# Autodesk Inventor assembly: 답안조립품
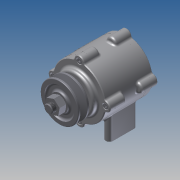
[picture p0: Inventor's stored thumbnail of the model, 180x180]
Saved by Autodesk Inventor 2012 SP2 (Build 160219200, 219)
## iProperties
Created: 2015-03
Part Number: 답안조립품
Document SubType Name: Assembly
Designer: Administrator
Author: Administrator
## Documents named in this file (11)
- C:\Users\Administrator\Desktop\450306V1034\답안조립품.iam
- C:\Users\Administrator\Desktop\450306V1034\본체.ipt
- C:\Users\Administrator\Desktop\450306V1034\커버.ipt
- C:\Users\Administrator\Desktop\450306V1034\오일실.ipt
- C:\Users\Administrator\Desktop\450306V1034\커버2.ipt
- C:\Users\Administrator\Desktop\450306V1034\축.ipt
- C:\Users\Administrator\Desktop\450306V1034\베어링 6204.ipt
- C:\Users\Administrator\Desktop\450306V1034\키(4 x 4 x 12).ipt
- C:\Users\Administrator\Desktop\450306V1034\V벨트풀리.ipt
- C:\Users\Administrator\Desktop\450306V1034\너트 M12x1.25.ipt
- C:\Users\Administrator\Desktop\450306V1034\M 4 x 12.ipt
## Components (14 placed, 6 different names)
1. KS B 2804 D D - 20 32 8:1
2. KS B 2023 6204 - 20 x 47 x 14:1
3. KS B 2023 6204 - 20 x 47 x 14:2
4. KS B 1311 (I) 4 x 4 x 12:1
5. 그루브 풀리1:1
6. KS B 1012 클래스 1 일반 - 미터 M12x1.25:1
7. KS B 1003 - 미터 M 4 x 12:1
8. KS B 1003 - 미터 M 4 x 12:3
9. KS B 1003 - 미터 M 4 x 12:4
10. KS B 1003 - 미터 M 4 x 12:5
11. KS B 1003 - 미터 M 4 x 12:2
12. KS B 1003 - 미터 M 4 x 12:6
13. KS B 1003 - 미터 M 4 x 12:7
14. KS B 1003 - 미터 M 4 x 12:8
